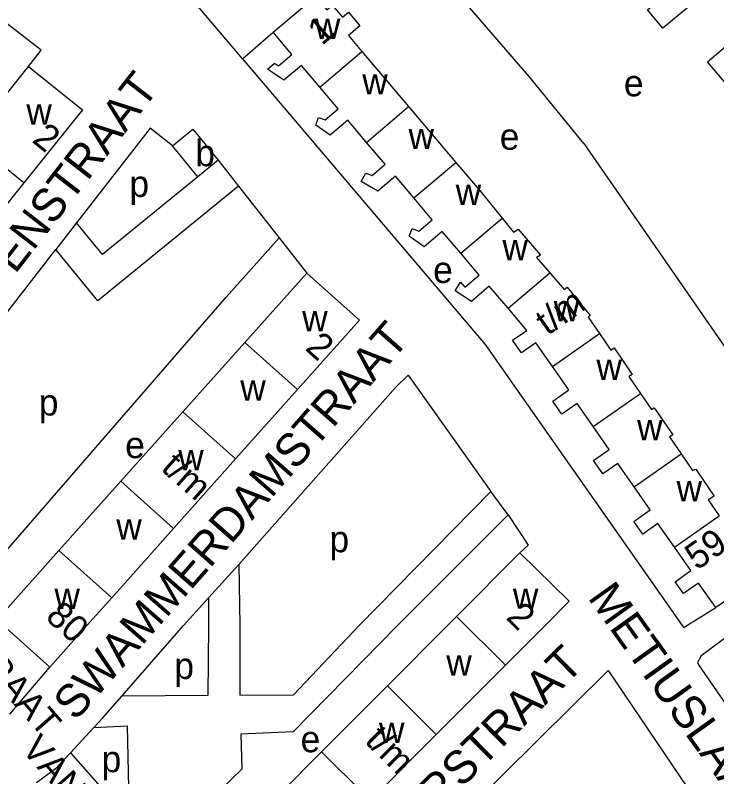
# Model space of a CAD drawing. Extents: x 159902 to 161769, y 383692 to 384875.
# Drawn here: x 160329.3 to 160435.6, y 384277.1 to 384392.4 of the extents above; entities that cross this region are included whole.
import ezdxf

# ---------------------------------------------------------------- set-up
doc = ezdxf.new("R2010")
doc.units = 0
for name, color, linetype in [('BLT_Basislijn', 7, 'Continuous'), ('BLT_Bebouwing', 7, 'Continuous'), ('BLT_Centroide', 7, 'Continuous'), ('BLT_Huisnummer_reeks', 7, 'Continuous'), ('BLT_Onderverdeling_panden', 7, 'Continuous'), ('BLT_Straatnaam', 7, 'Continuous'), ('BLT_Straatnaam_verkleind', 7, 'Continuous')]:
    doc.layers.add(name, color=color, linetype=linetype)

msp = doc.modelspace()

# ---------------------------------------------------------------- linework, layer by layer
at = {"layer": 'BLT_Basislijn'}
for p, q in [((160363.73, 384385.86), (160368.4, 384389.87)), ((160415.44, 384373.03), (160407.14, 384383.15)), ((160415.44, 384373.03), (160450.04, 384322.96)), ((160360.06, 384370.5), (160363.14, 384366.56)), ((160356.98, 384367.99), (160342.54, 384356.2)), ((160363.14, 384366.56), (160341.83, 384349.17)), ((160363.14, 384366.56), (160369.28, 384358.74)), ((160342.54, 384356.2), (160338.63, 384361)), ((160361.27, 384349.73), (160369.28, 384358.74)), ((160369.28, 384358.74), (160373.49, 384353.36)), ((160306.8, 384320.07), (160335.48, 384356.95)), ((160341.83, 384349.17), (160335.48, 384356.95)), ((160404, 384316.79), (160401.36, 384320.28)), ((160358.63, 384304.25), (160363.21, 384309.25)), ((160328.54, 384286.58), (160334.58, 384293.7)), ((160342.58, 384286.02), (160345.51, 384289.36)), ((160345.51, 384289.36), (160358.55, 384289.43)), ((160363.36, 384289.46), (160371.47, 384289.5)), ((160342.58, 384286.02), (160341.22, 384284.55)), ((160341.22, 384284.55), (160337.69, 384280.72)), ((160337.69, 384280.72), (160336.71, 384279.66)), ((160337.69, 384280.72), (160346.57, 384270.7))]:
    msp.add_line(p, q, dxfattribs=at)
for points in [[(160407.14, 384383.15), (160388.79, 384404.48), (160387.15, 384405.86)], [(160363.73, 384385.86), (160362.98, 384386.75), (160355.02, 384396.17), (160355.35, 384396.94), (160359.52, 384401.59)], [(160331.35, 384384.66), (160333.29, 384387.17), (160327.88, 384391.33)], [(160363.73, 384385.86), (160400.5, 384342.56), (160430.33, 384300), (160430.57, 384299.7), (160431.04, 384300), (160435.4, 384302.73)], [(160353.15, 384372.68), (160349.77, 384375.33), (160338.63, 384361)], [(160338.63, 384361), (160335.48, 384356.95)], [(160321.75, 384304.18), (160361.27, 384349.73)], [(160363.21, 384309.25), (160386.91, 384336.07), (160388.86, 384337.9), (160401.36, 384320.28)], [(160371.47, 384289.5), (160381.41, 384300), (160401.36, 384320.28)], [(160404, 384316.79), (160387.22, 384300), (160371.44, 384283.91)], [(160404, 384316.79), (160407, 384312.18), (160405.75, 384311)], [(160363.21, 384309.25), (160363.37, 384300), (160363.36, 384289.46)], [(160345.51, 384289.36), (160354.84, 384300), (160358.63, 384304.25)], [(160358.55, 384289.43), (160358.67, 384300), (160358.63, 384304.25)], [(160437.92, 384298.9), (160433.19, 384295.39), (160432.67, 384294.41), (160432.8, 384294.03), (160500, 384196.88), (160500.95, 384195.48)], [(160392.46, 384266.78), (160419.14, 384293.17), (160431.13, 384275.39)], [(160341.22, 384284.55), (160346.29, 384284.78), (160346.57, 384270.7)], [(160371.44, 384283.91), (160363.52, 384283.56), (160363.67, 384278.22), (160350.87, 384265.85)], [(160336.71, 384279.66), (160335.43, 384278.29), (160332.58, 384276.15)]]:
    msp.add_lwpolyline(points, dxfattribs=at)
at = {"layer": 'BLT_Bebouwing'}
for p, q in [((160381.84, 384386.97), (160388.9, 384378.62)), ((160322.49, 384373.61), (160331.35, 384384.66)), ((160388.9, 384378.62), (160396.05, 384370.15)), ((160330.65, 384367.06), (160321.81, 384356.05)), ((160364.11, 384342.86), (160373.49, 384353.36)), ((160354.73, 384332.36), (160364.11, 384342.86)), ((160372.07, 384335.75), (160362.7, 384325.23)), ((160345.34, 384321.85), (160354.73, 384332.36)), ((160362.7, 384325.23), (160353.32, 384314.72)), ((160335.96, 384311.35), (160345.34, 384321.85)), ((160353.32, 384314.72), (160343.95, 384304.21)), ((160396.15, 384301.36), (160405.75, 384311)), ((160442.62, 384307.71), (160435.4, 384302.73)), ((160435.4, 384302.73), (160432.8, 384306.44)), ((160403.55, 384293.98), (160393.08, 384283.49)), ((160375.73, 384280.89), (160385.69, 384290.87)), ((160393.08, 384283.49), (160383.12, 384273.51)), ((160365.77, 384270.9), (160375.73, 384280.89))]:
    msp.add_line(p, q, dxfattribs=at)
for points in [[(160435.26, 384397.06), (160427.4, 384390.47), (160425.06, 384393.25), (160427.08, 384394.96), (160424.93, 384397.49)], [(160368.4, 384389.87), (160372.54, 384393.38), (160374.8, 384395.3)], [(160374.8, 384395.3), (160376.53, 384393.25), (160377.35, 384393.95), (160378.88, 384392.14), (160379.8, 384392.92), (160381.54, 384390.86), (160379.8, 384389.39), (160381.84, 384386.97)], [(160375.46, 384381.55), (160372.67, 384384.85), (160370.03, 384382.6), (160367.56, 384384.28), (160368.62, 384385.17), (160369.18, 384384.77), (160371.24, 384386.52), (160368.4, 384389.87)], [(160438.13, 384380.7), (160434.17, 384385.4), (160436.54, 384387.4), (160440.36, 384390.62)], [(160331.35, 384384.66), (160339.51, 384378.11), (160330.65, 384367.06)], [(160382.51, 384373.19), (160379.68, 384376.53), (160377.05, 384374.3), (160374.85, 384375.79), (160375.26, 384376.95), (160376.28, 384376.58), (160378.26, 384378.26), (160375.46, 384381.55)], [(160353.15, 384372.68), (160356.23, 384375.19), (160360.06, 384370.5)], [(160356.98, 384367.99), (160353.15, 384372.68)], [(160389.7, 384364.76), (160386.9, 384368.05), (160384.24, 384365.79), (160381.71, 384367.26), (160382.43, 384368.53), (160383.37, 384368.19), (160385.34, 384369.86), (160382.51, 384373.19)], [(160360.06, 384370.5), (160356.98, 384367.99)], [(160396.05, 384370.15), (160399.89, 384365.62), (160403.05, 384361.7)], [(160396.8, 384356.39), (160394, 384359.69), (160391.28, 384357.37), (160389.01, 384358.96), (160389.43, 384360.12), (160390.47, 384359.74), (160392.49, 384361.47), (160389.7, 384364.76)], [(160403.05, 384361.7), (160404.78, 384359.56), (160405.47, 384360.02), (160408.85, 384356.12), (160408.27, 384355.73), (160410.27, 384353.42)], [(160403.96, 384348.05), (160401.12, 384351.4), (160398.43, 384349.1), (160395.94, 384350.72), (160396.78, 384352.01), (160397.43, 384351.25), (160399.6, 384353.09), (160396.8, 384356.39)], [(160373.49, 384353.36), (160381.45, 384346.27), (160372.07, 384335.75)], [(160410.27, 384353.42), (160412.45, 384350.89), (160412.9, 384351.27), (160416.4, 384346.97), (160416.11, 384346.71), (160417.8, 384344.24)], [(160410.69, 384339.26), (160408.19, 384342.84), (160405.99, 384341.3), (160404.65, 384343.2), (160406.81, 384344.71), (160403.96, 384348.05)], [(160417.8, 384344.24), (160419.52, 384341.71), (160420.01, 384342.04), (160422.74, 384338.04), (160422.25, 384337.71), (160424, 384335.14)], [(160416.85, 384330.13), (160414.41, 384333.61), (160412.13, 384332.01), (160410.75, 384333.99), (160413.19, 384335.69), (160410.69, 384339.26)], [(160424, 384335.14), (160425.67, 384332.7), (160426.1, 384332.99), (160428.89, 384328.88), (160428.42, 384328.56), (160430.15, 384326.01)], [(160423.04, 384321.03), (160420.58, 384324.55), (160418.3, 384322.96), (160416.89, 384324.98), (160419.28, 384326.65), (160416.85, 384330.13)], [(160430.15, 384326.01), (160431.87, 384323.49), (160432.38, 384323.68), (160435.15, 384319.61), (160434.28, 384319.02), (160435.92, 384316.61)], [(160429.15, 384311.88), (160426.65, 384315.45), (160424.38, 384313.85), (160423.03, 384315.78), (160425.5, 384317.51), (160423.04, 384321.03)], [(160326.57, 384300.84), (160335.96, 384311.35)], [(160432.8, 384306.44), (160430.51, 384304.84), (160429.25, 384306.64), (160431.65, 384308.31), (160429.15, 384311.88)], [(160405.75, 384311), (160413.22, 384303.67), (160409.56, 384300), (160403.55, 384293.98)], [(160343.95, 384304.21), (160340.2, 384300), (160334.58, 384293.7)], [(160334.58, 384293.7), (160326.57, 384300.84)], [(160385.69, 384290.87), (160394.79, 384300), (160396.15, 384301.36)]]:
    msp.add_lwpolyline(points, dxfattribs=at)
at = {"layer": 'BLT_Onderverdeling_panden'}
for p, q in [((160375.46, 384381.55), (160381.84, 384386.97)), ((160382.51, 384373.19), (160388.9, 384378.62)), ((160330.65, 384367.06), (160322.49, 384373.61)), ((160389.7, 384364.76), (160396.05, 384370.15)), ((160396.8, 384356.39), (160403.05, 384361.7)), ((160403.96, 384348.05), (160410.27, 384353.42)), ((160410.69, 384339.26), (160417.8, 384344.24)), ((160372.07, 384335.75), (160364.11, 384342.86)), ((160416.85, 384330.13), (160424, 384335.14)), ((160362.7, 384325.23), (160354.73, 384332.36)), ((160423.04, 384321.03), (160430.15, 384326.01)), ((160353.32, 384314.72), (160345.34, 384321.85)), ((160429.15, 384311.88), (160435.92, 384316.61)), ((160343.95, 384304.21), (160335.96, 384311.35)), ((160396.15, 384301.36), (160403.55, 384293.98)), ((160385.69, 384290.87), (160393.08, 384283.49)), ((160375.73, 384280.89), (160383.12, 384273.51))]:
    msp.add_line(p, q, dxfattribs=at)

# ---------------------------------------------------------------- texts
at = {"layer": 'BLT_Centroide'}
for s, p in [('w', (160374.7, 384388.83)), ('w', (160381.88, 384380.44)), ('e', (160421.5, 384380.16)), ('w', (160331.02, 384375.89)), ('w', (160388.89, 384372.16)), ('e', (160402.71, 384372.06)), ('b', (160356.61, 384369.58)), ('p', (160346.63, 384364.92)), ('w', (160396.03, 384363.7)), ('w', (160403.11, 384355.34)), ('e', (160392.62, 384351.88)), ('w', (160410.88, 384346.06)), ('w', (160372.78, 384344.55)), ('w', (160417.34, 384337.2)), ('w', (160363.41, 384334.05)), ('p', (160332.91, 384331.81)), ('w', (160423.5, 384328.06)), ('e', (160345.99, 384325.35)), ('w', (160354.02, 384323.53)), ('w', (160429.47, 384318.81)), ('w', (160344.64, 384313.02)), ('p', (160376.92, 384311.1)), ('w', (160335.27, 384302.52)), ('w', (160404.69, 384302.53)), ('p', (160353.43, 384291.9)), ('w', (160394.61, 384292.42)), ('w', (160384.41, 384282.2)), ('e', (160372.55, 384280.8)), ('p', (160342.42, 384277.78))]:
    msp.add_text(s, height=4, dxfattribs=at).set_placement(p)
at = {"layer": 'BLT_Huisnummer_reeks'}
for s, rotation, p in [('1', 40.3309, (160375.78, 384387.76)), ('2', 321.2581, (160331.72, 384373.34)), ('t/m', 34.9758, (160409.94, 384343.83)), ('2', 318.2243, (160373.08, 384341.86)), ('t/m', 318.2269, (160351.24, 384323.64)), ('59', 34.9758, (160432.57, 384308.27)), ('80', 318.2835, (160333.74, 384301.06)), ('2', 315.0475, (160403.49, 384301.1)), ('t/m', 315.0466, (160382.11, 384282.39))]:
    msp.add_text(s, height=4, rotation=rotation, dxfattribs=at).set_placement(p)
at = {"layer": 'BLT_Straatnaam'}
for s, height, rotation, p in [('VAN SWINDENSTRAAT', 5, 52.1284, (160306.06, 384323.22)), ('SWAMMERDAMSTRAAT', 4.9999, 48.7349, (160338.47, 384285.39)), ('METIUSLAAN', 5, 305.609, (160415.93, 384304.21)), ('DE SITTERSTRAAT', 5, 44.6923, (160372.06, 384250.72))]:
    msp.add_text(s, height=height, rotation=rotation, dxfattribs=at).set_placement(p)
at = {"layer": 'BLT_Straatnaam_verkleind'}
for s, p in [('BOSSCHASTRAAT', (160302.47, 384318.47)), ('VAN MARUMSTRAAT', (160330.15, 384281.21))]:
    msp.add_text(s, height=4, rotation=311.1484, dxfattribs=at).set_placement(p)

doc.saveas('drawing.dxf')
